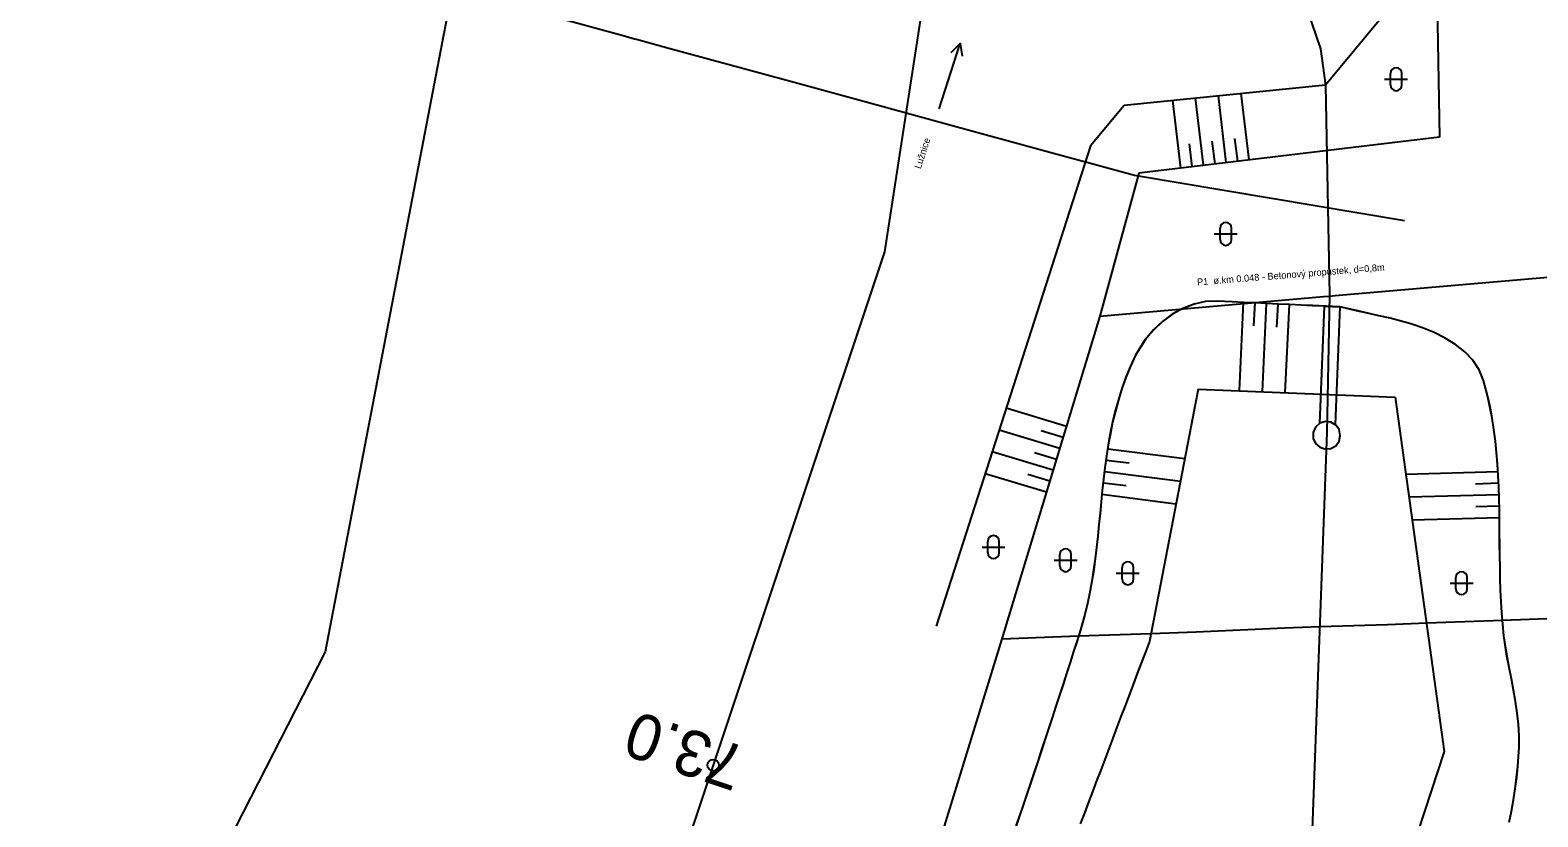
# Model space of a CAD drawing. Extents: x -737422 to -734235, y -1145631 to -1142623.
# Drawn here: x -735091.9 to -735026.3, y -1143056.7 to -1143022.4 of the extents above; entities that cross this region are included whole.
import ezdxf

# ---------------------------------------------------------------- set-up
doc = ezdxf.new("R2010")
doc.units = 0
for name, color, linetype in [('Vrstva 1', 7, 'Continuous'), ('Vrstva 2', 7, 'Continuous'), ('Vrstva 20', 7, 'Continuous'), ('Vrstva 21', 7, 'Continuous'), ('Vrstva 22', 7, 'Continuous'), ('Vrstva 3', 7, 'Continuous'), ('Vrstva 6', 7, 'Continuous'), ('Vrstva 7', 7, 'Continuous'), ('Vrstva 8', 7, 'Continuous')]:
    doc.layers.add(name, color=color, linetype=linetype)

# ---------------------------------------------------------------- blocks, each defined once
blk = doc.blocks.new('5.200')
at = {"layer": 'Vrstva 1'}
for radius in [0.5, 0.01]:
    blk.add_circle((0, 0), radius, dxfattribs=at)
blk = doc.blocks.new('3.160')
at = {"layer": 'Vrstva 1'}
for p, q in [((-1, 0), (1, 0)), ((-0.5, -0.5), (-0.5, 0.5)), ((0.5, -0.5), (0.5, 0.5))]:
    blk.add_line(p, q, dxfattribs=at)
for centre, start, end in [((0, 0.5), 0, 180), ((0, -0.5), 180, 360)]:
    blk.add_arc(centre, 0.5, start, end, dxfattribs=at)
blk = doc.blocks.new('8.021')
at = {"layer": 'Vrstva 1'}
blk.add_line((-3, 0), (3, 0), dxfattribs=at)
blk.add_lwpolyline([(2, 0.5), (3, 0), (2, -0.5)], dxfattribs=at)

msp = doc.modelspace()

# ---------------------------------------------------------------- linework, layer by layer
at = {"layer": 'Vrstva 2'}
for points in [[(-735014.111, -1142804.316), (-735027.1, -1142858.49), (-735039.95, -1142908.87), (-735047.15, -1142946.91), (-735047.51, -1142956.15), (-735047.84, -1142987.81), (-735049.04, -1142995.17), (-735054.73, -1143032.1), (-735062.19, -1143054.47)], [(-735047.84, -1142987.81), (-735035.74, -1143023.25), (-735035.52, -1143024.84), (-735035.34, -1143033.99), (-735035.46, -1143039.98), (-735036.11, -1143057.68), (-735035.82, -1143061.77), (-735035.37, -1143063.8), (-735034.62, -1143065.72), (-735027.19, -1143079.99), (-735026.74, -1143080.64), (-735026.77, -1143080.92), (-735029.28, -1143083.32), (-735034.74, -1143087.91), (-735037.38, -1143090.19), (-735037.41, -1143090.46), (-735036.99, -1143091.1)], [(-735062.19, -1143054.47), (-735067.52, -1143070.46), (-735083.15, -1143097.45), (-735109.45, -1143130.12), (-735117, -1143136.7), (-735131.48, -1143149.3), (-735161.32, -1143169.9), (-735197.01, -1143189.05), (-735200.15, -1143191.6), (-735226.32, -1143212.89), (-735242.32, -1143233.92), (-735251.01, -1143259.51), (-735252.721, -1143271.637)]]:
    msp.add_lwpolyline(points, dxfattribs=at)
at = {"layer": 'Vrstva 20'}
for points in [[(-735030.83, -1143011.41), (-735030.55, -1143027.1)], [(-735033.11, -1143021.94), (-735035.52, -1143024.84)], [(-735035.52, -1143024.84), (-735044.29, -1143025.72)], [(-735044.29, -1143025.72), (-735045.76, -1143027.49)], [(-735045.76, -1143027.49), (-735048.21, -1143035.12)], [(-735030.55, -1143027.1), (-735043.65, -1143028.67)], [(-735043.65, -1143028.67), (-735045.35, -1143034.91)], [(-735035.58, -1143034.47), (-735036.08, -1143034.45), (-735036.58, -1143034.42), (-735037.08, -1143034.4), (-735037.58, -1143034.38), (-735038.08, -1143034.35), (-735038.58, -1143034.33), (-735039.08, -1143034.31), (-735039.58, -1143034.28), (-735040.25, -1143034.25), (-735040.75, -1143034.27), (-735041.24, -1143034.38), (-735041.73, -1143034.57), (-735042.19, -1143034.82), (-735042.62, -1143035.14), (-735043.01, -1143035.51), (-735043.37, -1143035.92), (-735043.79, -1143036.61), (-735044.01, -1143037.09), (-735044.21, -1143037.57), (-735044.39, -1143038.06), (-735044.54, -1143038.55), (-735044.67, -1143039.04), (-735044.79, -1143039.53), (-735044.89, -1143040.02), (-735044.98, -1143040.52), (-735045.06, -1143041.01), (-735045.13, -1143041.51), (-735045.19, -1143042.01), (-735045.24, -1143042.5), (-735045.29, -1143043), (-735045.34, -1143043.5), (-735045.39, -1143043.99), (-735045.44, -1143044.49), (-735045.49, -1143044.98), (-735045.55, -1143045.47), (-735045.62, -1143045.96), (-735045.69, -1143046.45), (-735045.78, -1143046.94), (-735045.88, -1143047.42), (-735046, -1143047.9), (-735046.19, -1143048.57), (-735046.34, -1143049.05), (-735046.49, -1143049.52), (-735046.64, -1143050), (-735046.8, -1143050.47), (-735046.95, -1143050.95), (-735047.11, -1143051.42), (-735047.26, -1143051.9), (-735047.41, -1143052.37), (-735047.57, -1143052.85), (-735047.73, -1143053.32), (-735047.88, -1143053.79), (-735048.04, -1143054.27), (-735048.2, -1143054.74), (-735048.36, -1143055.22), (-735048.52, -1143055.69), (-735048.68, -1143056.17), (-735048.84, -1143056.64), (-735049, -1143057.11)], [(-735035.58, -1143034.47), (-735035.78, -1143039.58)], [(-735035.58, -1143034.47), (-735034.89, -1143034.5)], [(-735034.89, -1143034.5), (-735035.09, -1143039.63)], [(-735027.52, -1143056.95), (-735027.42, -1143056.47), (-735027.33, -1143055.98), (-735027.25, -1143055.5), (-735027.19, -1143055.01), (-735027.14, -1143054.52), (-735027.08, -1143053.68), (-735027.08, -1143053.19), (-735027.11, -1143052.69), (-735027.16, -1143052.2), (-735027.24, -1143051.7), (-735027.33, -1143051.21), (-735027.42, -1143050.71), (-735027.52, -1143050.21), (-735027.61, -1143049.72), (-735027.74, -1143048.83), (-735027.79, -1143048.33), (-735027.83, -1143047.84), (-735027.86, -1143047.34), (-735027.89, -1143046.84), (-735027.9, -1143046.34), (-735027.91, -1143045.84), (-735027.92, -1143045.34), (-735027.93, -1143044.85), (-735027.93, -1143044.35), (-735027.93, -1143043.85), (-735027.94, -1143043.35), (-735027.95, -1143042.85), (-735027.97, -1143042.35), (-735027.99, -1143041.85), (-735028.02, -1143041.35), (-735028.06, -1143040.85), (-735028.11, -1143040.35), (-735028.18, -1143039.85), (-735028.25, -1143039.35), (-735028.35, -1143038.86), (-735028.46, -1143038.36), (-735028.63, -1143037.71), (-735028.82, -1143037.24), (-735029.1, -1143036.83), (-735029.44, -1143036.46), (-735029.85, -1143036.14), (-735030.3, -1143035.86), (-735030.78, -1143035.62), (-735031.29, -1143035.41), (-735031.8, -1143035.24), (-735032.7, -1143035), (-735033.19, -1143034.89), (-735033.68, -1143034.78), (-735034.16, -1143034.67), (-735034.89, -1143034.5)], [(-735048.21, -1143035.12), (-735052.48, -1143048.41)], [(-735045.35, -1143034.91), (-735049.61, -1143048.97)], [(-735041.06, -1143038.08), (-735043.19, -1143049.08)], [(-735041.06, -1143038.08), (-735032.48, -1143038.43)], [(-735032.48, -1143038.43), (-735030.34, -1143053.87)], [(-735034.87, -1143040.1), (-735034.92, -1143039.85), (-735035.06, -1143039.65), (-735035.28, -1143039.53), (-735035.52, -1143039.5), (-735035.76, -1143039.57), (-735035.95, -1143039.74), (-735036.06, -1143039.98), (-735036.05, -1143040.23), (-735035.95, -1143040.45), (-735035.77, -1143040.61), (-735035.54, -1143040.69), (-735035.29, -1143040.67), (-735035.07, -1143040.55), (-735034.92, -1143040.35), (-735034.87, -1143040.11), (-735034.87, -1143040.1)], [(-735049.61, -1143048.97), (-735054.06, -1143063.41)], [(-735043.19, -1143049.08), (-735043.36, -1143049.55), (-735043.54, -1143050.02), (-735043.72, -1143050.48), (-735043.9, -1143050.95), (-735044.07, -1143051.42), (-735044.25, -1143051.89), (-735044.43, -1143052.35), (-735044.6, -1143052.82), (-735044.78, -1143053.29), (-735044.96, -1143053.76), (-735045.13, -1143054.22), (-735045.31, -1143054.69), (-735045.49, -1143055.16), (-735045.67, -1143055.63), (-735045.84, -1143056.09), (-735046.02, -1143056.56), (-735046.2, -1143057.03)], [(-735030.34, -1143053.87), (-735034.05, -1143065.18)]]:
    msp.add_lwpolyline(points, dxfattribs=at)
at = {"layer": 'Vrstva 21'}
for points in [[(-735041.82, -1143028.45), (-735042.17, -1143025.51)], [(-735040.83, -1143028.33), (-735041.18, -1143025.41)], [(-735039.84, -1143028.21), (-735040.18, -1143025.31)], [(-735038.84, -1143028.09), (-735039.19, -1143025.21)], [(-735041.32, -1143028.39), (-735041.44, -1143027.4)], [(-735040.33, -1143028.27), (-735040.45, -1143027.28)], [(-735039.34, -1143028.15), (-735039.46, -1143027.16)], [(-735039.1, -1143034.31), (-735039.28, -1143038.15)], [(-735038.6, -1143034.33), (-735038.65, -1143035.33)], [(-735038.1, -1143034.35), (-735038.28, -1143038.19)], [(-735037.6, -1143034.38), (-735037.65, -1143035.38)], [(-735037.1, -1143034.4), (-735037.29, -1143038.23)], [(-735046.8, -1143039.71), (-735049.43, -1143038.91)], [(-735047.09, -1143040.67), (-735049.74, -1143039.87)], [(-735046.95, -1143040.19), (-735047.91, -1143039.9)], [(-735047.38, -1143041.62), (-735050.04, -1143040.82)], [(-735047.24, -1143041.15), (-735048.2, -1143040.86)], [(-735045.07, -1143041.18), (-735044.07, -1143041.3)], [(-735045, -1143040.68), (-735041.65, -1143041.11)], [(-735047.67, -1143042.58), (-735050.35, -1143041.77)], [(-735047.53, -1143042.1), (-735048.49, -1143041.81)], [(-735045.13, -1143041.67), (-735041.84, -1143042.09)], [(-735028, -1143041.69), (-735032.01, -1143041.8)], [(-735045.19, -1143042.17), (-735044.2, -1143042.29)], [(-735027.98, -1143042.19), (-735028.98, -1143042.22)], [(-735045.26, -1143042.66), (-735042.03, -1143043.08)], [(-735027.97, -1143042.69), (-735031.87, -1143042.8)], [(-735027.96, -1143043.19), (-735028.96, -1143043.22)], [(-735027.94, -1143043.69), (-735031.74, -1143043.8)]]:
    msp.add_lwpolyline(points, dxfattribs=at)
at = {"layer": 'Vrstva 3'}
for points in [[(-735034.121, -1142807.443), (-735041.41, -1142833.15), (-735049.67, -1142873.94), (-735063.61, -1142929.72), (-735068.77, -1142951.92), (-735071.87, -1143011.83), (-735079.1, -1143049.53), (-735090.46, -1143071.74), (-735105.06, -1143095.74), (-735128.12, -1143122.71), (-735156.5, -1143145.42), (-735208.29, -1143180.56), (-735229.22, -1143198.3), (-735243.77, -1143211.78), (-735256.18, -1143225.98), (-735267.54, -1143251.18), (-735270.892, -1143271.893)], [(-735030.83, -1143011.41), (-735030.55, -1143027.1)], [(-735030.55, -1143027.1), (-735043.65, -1143028.67)], [(-735043.65, -1143028.67), (-735045.35, -1143034.91)], [(-735034.89, -1143034.5), (-735036.079, -1143034.446), (-735036.579, -1143034.423), (-735037.078, -1143034.399), (-735037.578, -1143034.376), (-735038.077, -1143034.352), (-735038.577, -1143034.329), (-735039.076, -1143034.305), (-735039.576, -1143034.282), (-735040.25, -1143034.25), (-735040.75, -1143034.272), (-735041.244, -1143034.38), (-735041.726, -1143034.566), (-735042.187, -1143034.821), (-735042.619, -1143035.137), (-735043.015, -1143035.506), (-735043.365, -1143035.92), (-735043.79, -1143036.61), (-735044.013, -1143037.09), (-735044.211, -1143037.573), (-735044.385, -1143038.059), (-735044.539, -1143038.547), (-735044.674, -1143039.037), (-735044.791, -1143039.529), (-735044.893, -1143040.022), (-735044.982, -1143040.517), (-735045.059, -1143041.012), (-735045.126, -1143041.509), (-735045.186, -1143042.005), (-735045.24, -1143042.502), (-735045.29, -1143042.999), (-735045.338, -1143043.495), (-735045.386, -1143043.991), (-735045.436, -1143044.486), (-735045.49, -1143044.98), (-735045.549, -1143045.472), (-735045.616, -1143045.963), (-735045.693, -1143046.452), (-735045.781, -1143046.938), (-735045.882, -1143047.422), (-735045.998, -1143047.903), (-735046.19, -1143048.57), (-735046.341, -1143049.045), (-735046.492, -1143049.52), (-735046.644, -1143049.995), (-735046.797, -1143050.47), (-735046.951, -1143050.945), (-735047.105, -1143051.42), (-735047.259, -1143051.895), (-735047.414, -1143052.37), (-735047.57, -1143052.845), (-735047.726, -1143053.319), (-735047.883, -1143053.794), (-735048.04, -1143054.269), (-735048.198, -1143054.743), (-735048.357, -1143055.218), (-735048.515, -1143055.692), (-735048.675, -1143056.166), (-735048.835, -1143056.64), (-735048.995, -1143057.114)], [(-735027.518, -1143056.954), (-735027.418, -1143056.469), (-735027.329, -1143055.982), (-735027.251, -1143055.495), (-735027.186, -1143055.007), (-735027.135, -1143054.517), (-735027.08, -1143053.68), (-735027.078, -1143053.187), (-735027.108, -1143052.693), (-735027.163, -1143052.198), (-735027.237, -1143051.702), (-735027.325, -1143051.206), (-735027.42, -1143050.71), (-735027.516, -1143050.214), (-735027.608, -1143049.718), (-735027.74, -1143048.83), (-735027.792, -1143048.334), (-735027.832, -1143047.837), (-735027.863, -1143047.34), (-735027.886, -1143046.842), (-735027.902, -1143046.343), (-735027.913, -1143045.844), (-735027.92, -1143045.344), (-735027.925, -1143044.845), (-735027.929, -1143044.345), (-735027.934, -1143043.845), (-735027.941, -1143043.345), (-735027.952, -1143042.845), (-735027.968, -1143042.345), (-735027.99, -1143041.845), (-735028.021, -1143041.346), (-735028.061, -1143040.846), (-735028.112, -1143040.348), (-735028.176, -1143039.85), (-735028.254, -1143039.352), (-735028.347, -1143038.855), (-735028.457, -1143038.359), (-735028.63, -1143037.71), (-735028.821, -1143037.242), (-735029.096, -1143036.827), (-735029.442, -1143036.459), (-735029.847, -1143036.138), (-735030.298, -1143035.858), (-735030.782, -1143035.617), (-735031.288, -1143035.411), (-735031.803, -1143035.238), (-735032.7, -1143035), (-735033.187, -1143034.889), (-735033.675, -1143034.777), (-735034.162, -1143034.666), (-735034.89, -1143034.5)], [(-735045.35, -1143034.91), (-735049.61, -1143048.97)], [(-735049.61, -1143048.97), (-735054.06, -1143063.41)]]:
    msp.add_lwpolyline(points, dxfattribs=at)
at = {"layer": 'Vrstva 8'}
for points in [[(-735087.87, -1143016.15), (-735080.82, -1143017.98), (-735074.96, -1143020.27), (-735070.11, -1143021.59), (-735066.12, -1143022.68), (-735065.62, -1143022.82), (-735065.54, -1143022.84), (-735064.12, -1143023.23), (-735059.15, -1143024.58), (-735055.53, -1143025.57), (-735051.72, -1143026.61), (-735047.69, -1143027.71), (-735046.67, -1143027.99), (-735045.91, -1143028.19), (-735043.84, -1143028.76), (-735032.07, -1143030.74)], [(-735045.35, -1143034.91), (-735035.6, -1143034.05), (-735035.34, -1143034.03), (-735035.09, -1143034.01), (-735023.81, -1143033.03)], [(-735049.61, -1143048.97), (-735046.28, -1143048.84), (-735043.11, -1143048.73), (-735041.15, -1143048.66), (-735037.3, -1143048.48), (-735035.77, -1143048.43), (-735032.81, -1143048.34), (-735031.1, -1143048.27), (-735027.79, -1143048.15), (-735020.89, -1143047.89)]]:
    msp.add_lwpolyline(points, dxfattribs=at)

# ---------------------------------------------------------------- block references
at = {"layer": 'Vrstva 20', "xscale": 0.49999999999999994, "yscale": 0.5000000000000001, "rotation": 72.19818383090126}
msp.add_blockref('8.021', (-735051.89, -1143024.45), dxfattribs=at)
at = {"layer": 'Vrstva 20', "xscale": 0.5, "yscale": 0.5}
for p in [(-735032.44, -1143024.58), (-735039.86, -1143031.32), (-735049.98, -1143044.97), (-735046.84, -1143045.54), (-735044.13, -1143046.11), (-735029.59, -1143046.54)]:
    msp.add_blockref('3.160', p, dxfattribs=at)
at = {"layer": 'Vrstva 6', "xscale": 0.5, "yscale": 0.5}
msp.add_blockref('5.200', (-735062.19, -1143054.47), dxfattribs=at)

# ---------------------------------------------------------------- texts
at = {"layer": 'Vrstva 22'}
for s, rotation, p in [('Lužnice', 72.072, (-735053.15, -1143028.51)), ('P1  ø.km 0.048 - Betonový propustek, d=0,8m', 4.554, (-735041.1, -1143033.57))]:
    msp.add_text(s, height=0.3, rotation=rotation, dxfattribs=at).set_placement(p)
at = {"layer": 'Vrstva 7'}
msp.add_text('  73.0', height=2, rotation=161.557, dxfattribs=at).set_placement((-735059.24, -1143054.2))

doc.saveas('drawing.dxf')
